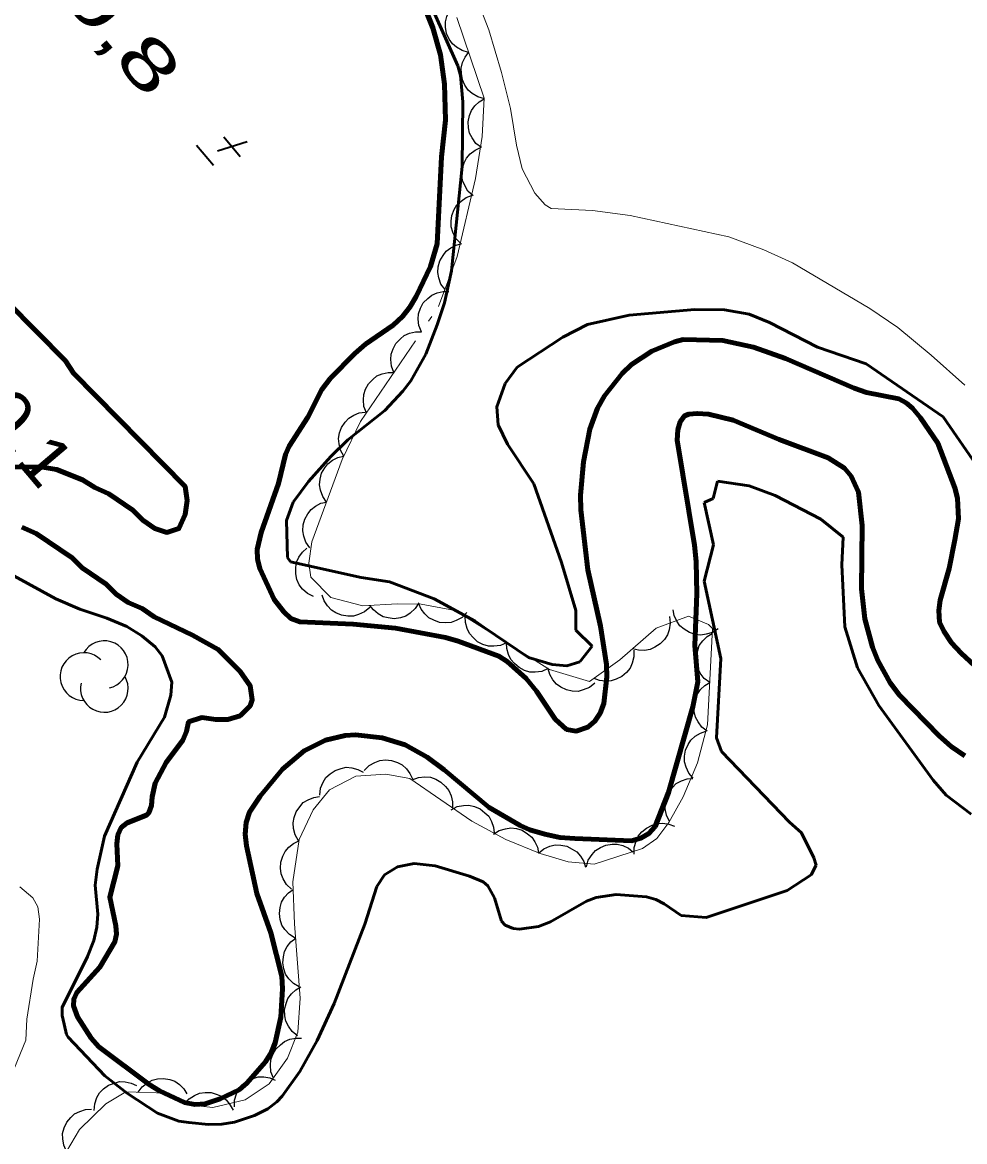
# Model space of a CAD drawing. Extents: x 386081 to 389416, y 5130568 to 5134082.
# Drawn here: x 387180.4 to 387238.2, y 5131872.3 to 5131941 of the extents above; entities that cross this region are included whole.
import ezdxf
from ezdxf.enums import TextEntityAlignment as Align

# ---------------------------------------------------------------- set-up
doc = ezdxf.new("R2010")
doc.units = 0
doc.header["$LTSCALE"] = 1.2
for name, pattern in [('DASH_DOUBLE_DOT', [9.2, 5, -1.2, 0.3, -1.2, 0.3, -1.2]), ('DOT_DASHED', [7.7, 5, -1.2, 0.3, -1.2]), ('LONG_DASHED', [7.5, 6, -1.5])]:
    doc.linetypes.add(name, pattern=pattern)
for name, color, linetype, lineweight in [('1', 7, 'Continuous', 53), ('2', 7, 'Continuous', 13), ('3', 7, 'Continuous', 140), ('4', 7, 'DASH_DOUBLE_DOT', 53), ('44', 7, 'Continuous', 25)]:
    doc.layers.add(name, color=color, linetype=linetype, lineweight=lineweight)

msp = doc.modelspace()

# ---------------------------------------------------------------- linework, layer by layer
at = {"layer": '1', "linetype": 'LONG_DASHED'}
for points in [[(387210.13, 5131915.13), (387211.73, 5131912.69), (387213.43, 5131907.87), (387214.31, 5131904.93), (387214.31, 5131903.72), (387215.31, 5131902.74), (387214.57, 5131901.78), (387213.77, 5131901.53), (387212.87, 5131901.62), (387211.41, 5131902.05), (387208.69, 5131903.88), (387208.13, 5131904.28), (387205.62, 5131905.65), (387202.88, 5131906.69), (387201.14, 5131906.95), (387196.81, 5131907.91), (387196.62, 5131908.18), (387196.56, 5131910.44), (387196.98, 5131911.58), (387197.91, 5131912.84), (387199.29, 5131914.37), (387200.32, 5131915.4), (387202.6, 5131917.2), (387203.71, 5131918.38), (387204.19, 5131919.01), (387205.11, 5131920.65), (387205.81, 5131922.45), (387206.25, 5131923.79), (387206.69, 5131925.75), (387207.34, 5131932.16), (387207.39, 5131936.13), (387207.24, 5131937.74), (387207.08, 5131938.34), (387205.57, 5131941.72)], [(387239.07, 5131913.57), (387236.84, 5131916.8), (387232.13, 5131920.05), (387229.14, 5131921.07), (387226.19, 5131922.59), (387224.94, 5131923.11), (387223.44, 5131923.37), (387221.62, 5131923.38), (387217.58, 5131923.05), (387215.03, 5131922.46), (387213.52, 5131921.7), (387210.72, 5131919.86), (387209.97, 5131918.84), (387209.46, 5131917.42), (387209.55, 5131916.32), (387210.13, 5131915.13)], [(387182.92, 5131879.54), (387183.07, 5131878.91), (387183.18, 5131878.75), (387185.43, 5131876.37), (387186.82, 5131875.29), (387188.66, 5131874.08), (387189.97, 5131873.59), (387190.57, 5131873.51), (387191.79, 5131873.4), (387192.59, 5131873.42), (387193.38, 5131873.54), (387194.6, 5131873.95), (387195.42, 5131874.36), (387195.98, 5131874.78), (387196.31, 5131875.13), (387197.39, 5131876.65), (387198.44, 5131878.55), (387199.48, 5131880.82), (387201.38, 5131885.68), (387202.11, 5131888), (387202.57, 5131888.71), (387203.38, 5131889.2), (387204.4, 5131889.41), (387205.69, 5131889.26), (387207.8, 5131888.63), (387208.63, 5131888.29), (387208.92, 5131888.03), (387209.32, 5131887.3), (387209.76, 5131885.86), (387209.99, 5131885.63), (387210.47, 5131885.42), (387210.85, 5131885.37), (387212.02, 5131885.55), (387212.77, 5131885.82), (387214.96, 5131887.09), (387215.56, 5131887.32), (387216.79, 5131887.51), (387218.66, 5131887.36), (387219.23, 5131887.19), (387219.73, 5131886.93), (387220.78, 5131886.22), (387222.32, 5131886.09), (387227.27, 5131887.74), (387228.76, 5131888.72), (387229.05, 5131889.3), (387228.92, 5131889.75), (387228.15, 5131891.29), (387227.43, 5131891.95), (387223.26, 5131896.28), (387222.95, 5131897.12), (387223.22, 5131901.98), (387222.18, 5131906.72), (387222.76, 5131908.96), (387222.19, 5131911.55), (387222.75, 5131911.8), (387223, 5131912.86), (387224.95, 5131912.58), (387226.55, 5131911.98), (387229.35, 5131910.53), (387230.72, 5131909.43), (387230.63, 5131907.72), (387230.81, 5131903.92), (387231.6, 5131901.41), (387232.9, 5131899.09), (387236.23, 5131894.51), (387237.04, 5131893.59), (387238.56, 5131892.44)]]:
    msp.add_lwpolyline(points, dxfattribs=at)
at = {"layer": '1'}
msp.add_lwpolyline([(387178.97, 5131907.52), (387182.41, 5131905.64), (387183.89, 5131905.01), (387185.55, 5131904.45), (387186.78, 5131903.94), (387187.7, 5131903.38), (387188.5, 5131902.7), (387188.93, 5131902.14), (387189.53, 5131900.53), (387189.47, 5131899.73), (387189.09, 5131898.38), (387187.4, 5131895.63), (387185.4, 5131891.09), (387184.95, 5131889.06), (387184.82, 5131888.07), (387185, 5131886.29), (387184.93, 5131885.49), (387184.74, 5131884.69), (387184.36, 5131883.71), (387182.8, 5131880.58), (387182.8, 5131880.09), (387182.92, 5131879.54)], dxfattribs=at)
at = {"layer": '2', "linetype": 'LONG_DASHED'}
msp.add_lwpolyline([(387238.17, 5131918.74), (387236.12, 5131920.58), (387234.06, 5131922.28), (387232.35, 5131923.45), (387227.6, 5131926.26), (387225.85, 5131927.04), (387223.7, 5131927.84), (387217.65, 5131929.15), (387215.33, 5131929.46), (387212.81, 5131929.59), (387212.44, 5131929.8), (387211.8, 5131930.53), (387211.03, 5131932.01), (387210.67, 5131933.47), (387210.31, 5131935.72), (387209.75, 5131937.92), (387208.98, 5131940.54), (387208.18, 5131942.59)], dxfattribs=at)
at = {"layer": '2'}
msp.add_lwpolyline([(387180.21, 5131887.98), (387181, 5131887.3), (387181.31, 5131886.74), (387181.42, 5131886), (387181.28, 5131883.42), (387181.03, 5131882.32), (387180.64, 5131879.86), (387180.57, 5131878.57), (387178.2, 5131872.82)], dxfattribs=at)
at = {"layer": '3', "lineweight": 35}
for p, q in [((387194.15, 5131933.68), (387192.33, 5131933.11)), ((387192.72, 5131933.97), (387193.73, 5131932.78)), ((387191.05, 5131933.47), (387192.09, 5131932.25))]:
    msp.add_line(p, q, dxfattribs=at)
at = {"layer": '4', "linetype": 'Continuous', "lineweight": 90}
for points in [[(387199.26, 5131919.17), (387200.76, 5131920.69), (387201.41, 5131921.26), (387203.11, 5131922.43), (387203.68, 5131922.96), (387204.14, 5131923.54), (387204.52, 5131924.19), (387205.39, 5131926.03), (387205.8, 5131927.42), (387206.07, 5131932.76), (387206.31, 5131935.01), (387206.26, 5131937.22), (387206.02, 5131939), (387205.54, 5131940.66), (387204.83, 5131942.48)], [(387179.45, 5131923.83), (387183, 5131920.23), (387183.49, 5131919.49), (387190.35, 5131912.53), (387190.47, 5131911.67), (387190.34, 5131910.81), (387189.97, 5131909.95), (387189.22, 5131909.71), (387188.49, 5131909.96), (387187.75, 5131910.46), (387187.14, 5131911.08), (387185.66, 5131912.08), (387184.8, 5131912.46), (387184.06, 5131912.95), (387182.46, 5131913.58), (387181.6, 5131913.71), (387179.63, 5131913.73)], [(387239.89, 5131900.51), (387237.95, 5131902.3), (387237.37, 5131902.95), (387236.89, 5131903.66), (387236.63, 5131904.2), (387236.58, 5131904.93), (387236.67, 5131905.55), (387237.22, 5131907.51), (387237.57, 5131909.25), (387237.78, 5131910.55), (387237.72, 5131911.82), (387237.57, 5131912.44), (387236.52, 5131915.19), (387235.46, 5131916.75), (387234.96, 5131917.34), (387234.57, 5131917.67), (387234.13, 5131917.9), (387232.15, 5131918.3), (387231.39, 5131918.57), (387227.18, 5131920.38), (387225.22, 5131921.07), (387223.34, 5131921.48), (387220.9, 5131921.54), (387220.36, 5131921.41), (387218.97, 5131920.83), (387217.73, 5131920.01), (387217.15, 5131919.46), (387216.08, 5131918.09), (387215.65, 5131917.34), (387215.18, 5131916.04), (387214.78, 5131914.05), (387214.6, 5131911.99), (387214.63, 5131911.09), (387215.05, 5131907.42), (387215.83, 5131903.96), (387216.19, 5131901.61), (387216.22, 5131900.86), (387216.03, 5131899.21), (387215.81, 5131898.63), (387215.49, 5131898.13), (387215.06, 5131897.76), (387214.33, 5131897.53), (387213.75, 5131897.63), (387213.05, 5131898.26), (387211.91, 5131899.97), (387211.27, 5131900.76), (387210.11, 5131901.8), (387209.59, 5131902.13), (387207.1, 5131903.05), (387206.33, 5131903.26), (387203.26, 5131903.84), (387200.66, 5131904.09), (387197.39, 5131904.22), (387196.83, 5131904.44), (387196.4, 5131904.84), (387195.8, 5131905.59), (387194.94, 5131907.51), (387194.79, 5131908.07), (387194.77, 5131908.66), (387195.02, 5131909.71), (387196.07, 5131912.71), (387196.51, 5131914.49), (387196.72, 5131915), (387197.87, 5131916.78), (387198.74, 5131918.49), (387199.26, 5131919.17)], [(387190.94, 5131874.62), (387191.57, 5131874.67), (387192.5, 5131874.96), (387193.66, 5131875.53), (387194.14, 5131875.93), (387195.27, 5131877.24), (387195.64, 5131877.83), (387195.88, 5131878.41), (387196.22, 5131879.97), (387196.33, 5131881.72), (387196.27, 5131882.49), (387195.6, 5131885.16), (387194.74, 5131887.57), (387194.12, 5131890.48), (387194.04, 5131891.21), (387194.1, 5131891.92), (387194.29, 5131892.55), (387194.95, 5131893.53), (387196.33, 5131895.19), (387197.64, 5131896.32), (387198.96, 5131896.97), (387200.17, 5131897.26), (387200.8, 5131897.29), (387202.43, 5131897.11), (387203.85, 5131896.69), (387205.19, 5131895.92), (387206.23, 5131895.15), (387208.99, 5131892.84), (387210.9, 5131891.74), (387211.49, 5131891.47), (387212.42, 5131891.2), (387213.33, 5131891.01), (387214.26, 5131890.94), (387217.74, 5131890.8), (387218.3, 5131890.95), (387218.8, 5131891.25), (387219.18, 5131891.68), (387219.99, 5131893.76), (387221.49, 5131899.01), (387221.79, 5131900.55), (387221.61, 5131902.8), (387221.74, 5131905.95), (387221.69, 5131907.92), (387221.6, 5131908.93), (387220.53, 5131915.37), (387220.58, 5131916), (387220.72, 5131916.5), (387220.98, 5131916.86), (387221.25, 5131916.97), (387221.76, 5131917.01), (387222.45, 5131916.97), (387223.96, 5131916.61), (387226.78, 5131915.42), (387229.8, 5131914.29), (387230.8, 5131913.65), (387231.2, 5131913.16), (387231.65, 5131912.19), (387231.89, 5131910.13), (387231.83, 5131906.26), (387232.05, 5131904.42), (387232.52, 5131902.67), (387232.84, 5131901.86), (387233.59, 5131900.49), (387234.17, 5131899.73), (387236.61, 5131897.23), (387237.34, 5131896.59), (387238.17, 5131896.01)], [(387180.34, 5131910.03), (387181.2, 5131909.65), (387183.41, 5131908.16), (387184.03, 5131907.54), (387185.5, 5131906.54), (387186.11, 5131905.92), (387186.85, 5131905.42), (387187.71, 5131905.04), (387188.45, 5131904.54), (387190.79, 5131903.42), (387192.38, 5131902.54), (387193.73, 5131901.18), (387194.34, 5131900.31), (387194.46, 5131899.45), (387194.34, 5131899.08), (387193.72, 5131898.47), (387192.97, 5131898.23), (387192.23, 5131898.23), (387191.37, 5131898.36), (387190.56, 5131898.09), (387190.44, 5131897.51), (387190.2, 5131896.97), (387189.18, 5131895.61), (387188.51, 5131894.33), (387188.32, 5131893.5), (387188.29, 5131892.96), (387188.12, 5131892.51), (387187.97, 5131892.36), (387186.8, 5131891.9), (387186.42, 5131891.61), (387186.22, 5131891.16), (387186.15, 5131890.62), (387186.21, 5131889.26), (387185.72, 5131887.34), (387186.1, 5131885.59), (387186.14, 5131885.07), (387186.04, 5131884.59), (387185.11, 5131883.04), (387183.7, 5131881.5), (387183.52, 5131881.09), (387183.5, 5131880.68), (387183.75, 5131879.99), (387184.58, 5131878.7), (387185.05, 5131878.16), (387188.14, 5131875.84), (387188.78, 5131875.45), (387190.31, 5131874.75), (387190.94, 5131874.62)]]:
    msp.add_lwpolyline(points, dxfattribs=at)
at = {"layer": '44'}
for points in [[(387207.74, 5131939.16), (387207.34, 5131939.27), (387206.99, 5131939.48), (387206.74, 5131939.69), (387206.54, 5131939.98), (387206.39, 5131940.32), (387206.33, 5131940.7), (387206.31, 5131941.03), (387206.4, 5131941.37), (387206.55, 5131941.71), (387206.77, 5131941.99)], [(387208.71, 5131936.32), (387208.31, 5131936.43), (387207.96, 5131936.64), (387207.71, 5131936.85), (387207.51, 5131937.15), (387207.36, 5131937.48), (387207.3, 5131937.86), (387207.28, 5131938.19), (387207.37, 5131938.53), (387207.52, 5131938.87), (387207.74, 5131939.16)], [(387208.52, 5131933.32), (387208.19, 5131933.58), (387207.95, 5131933.91), (387207.8, 5131934.2), (387207.73, 5131934.54), (387207.72, 5131934.91), (387207.8, 5131935.29), (387207.91, 5131935.59), (387208.12, 5131935.88), (387208.39, 5131936.13), (387208.7, 5131936.32)], [(387208.01, 5131930.36), (387207.7, 5131930.64), (387207.5, 5131930.99), (387207.37, 5131931.3), (387207.33, 5131931.65), (387207.35, 5131932.02), (387207.47, 5131932.38), (387207.61, 5131932.68), (387207.84, 5131932.94), (387208.13, 5131933.17), (387208.46, 5131933.33)], [(387207.23, 5131927.46), (387206.94, 5131927.77), (387206.77, 5131928.13), (387206.67, 5131928.45), (387206.66, 5131928.8), (387206.71, 5131929.16), (387206.86, 5131929.52), (387207.02, 5131929.8), (387207.28, 5131930.04), (387207.58, 5131930.25), (387207.92, 5131930.38)], [(387206.29, 5131924.62), (387206.04, 5131924.95), (387205.91, 5131925.34), (387205.85, 5131925.66), (387205.88, 5131926.01), (387205.98, 5131926.37), (387206.17, 5131926.7), (387206.36, 5131926.97), (387206.65, 5131927.18), (387206.98, 5131927.34), (387207.33, 5131927.43)], [(387204.84, 5131922.01), (387204.69, 5131922.4), (387204.65, 5131922.8), (387204.67, 5131923.13), (387204.78, 5131923.46), (387204.96, 5131923.79), (387205.23, 5131924.06), (387205.48, 5131924.27), (387205.8, 5131924.41), (387206.17, 5131924.49), (387206.53, 5131924.49)], [(387203.16, 5131919.53), (387203, 5131919.91), (387202.97, 5131920.32), (387202.98, 5131920.65), (387203.1, 5131920.98), (387203.28, 5131921.3), (387203.55, 5131921.58), (387203.79, 5131921.79), (387204.12, 5131921.93), (387204.48, 5131922.01), (387204.84, 5131922.01)], [(387201.47, 5131917.04), (387201.32, 5131917.43), (387201.28, 5131917.84), (387201.3, 5131918.17), (387201.42, 5131918.5), (387201.6, 5131918.82), (387201.86, 5131919.1), (387202.11, 5131919.31), (387202.44, 5131919.44), (387202.8, 5131919.53), (387203.16, 5131919.53)], [(387200.09, 5131914.39), (387199.88, 5131914.75), (387199.79, 5131915.14), (387199.75, 5131915.47), (387199.82, 5131915.82), (387199.95, 5131916.16), (387200.17, 5131916.48), (387200.39, 5131916.72), (387200.69, 5131916.9), (387201.03, 5131917.04), (387201.39, 5131917.09)], [(387199.03, 5131911.58), (387198.79, 5131911.92), (387198.66, 5131912.31), (387198.59, 5131912.63), (387198.63, 5131912.98), (387198.72, 5131913.34), (387198.92, 5131913.67), (387199.11, 5131913.93), (387199.39, 5131914.14), (387199.72, 5131914.31), (387200.07, 5131914.4)], [(387198, 5131908.77), (387197.75, 5131909.11), (387197.62, 5131909.49), (387197.56, 5131909.81), (387197.59, 5131910.17), (387197.69, 5131910.52), (387197.88, 5131910.85), (387198.07, 5131911.12), (387198.35, 5131911.33), (387198.68, 5131911.5), (387199.03, 5131911.58)], [(387198.23, 5131905.78), (387197.85, 5131905.96), (387197.55, 5131906.24), (387197.34, 5131906.49), (387197.21, 5131906.82), (387197.13, 5131907.18), (387197.14, 5131907.56), (387197.18, 5131907.88), (387197.33, 5131908.2), (387197.54, 5131908.51), (387197.81, 5131908.75)], [(387201.67, 5131905.11), (387201.35, 5131904.84), (387200.98, 5131904.67), (387200.67, 5131904.57), (387200.32, 5131904.57), (387199.95, 5131904.63), (387199.6, 5131904.79), (387199.32, 5131904.95), (387199.08, 5131905.21), (387198.88, 5131905.52), (387198.76, 5131905.86)], [(387204.68, 5131905.4), (387204.46, 5131905.04), (387204.16, 5131904.77), (387203.89, 5131904.58), (387203.55, 5131904.48), (387203.18, 5131904.42), (387202.8, 5131904.47), (387202.49, 5131904.54), (387202.18, 5131904.72), (387201.9, 5131904.96), (387201.68, 5131905.24)], [(387207.63, 5131904.8), (387207.34, 5131904.5), (387206.98, 5131904.31), (387206.67, 5131904.19), (387206.32, 5131904.16), (387205.96, 5131904.19), (387205.6, 5131904.33), (387205.3, 5131904.47), (387205.05, 5131904.71), (387204.83, 5131905.01), (387204.68, 5131905.34)], [(387223.05, 5131903.81), (387222.7, 5131903.58), (387222.31, 5131903.47), (387221.98, 5131903.42), (387221.64, 5131903.46), (387221.28, 5131903.57), (387220.96, 5131903.78), (387220.7, 5131903.98), (387220.51, 5131904.27), (387220.35, 5131904.61), (387220.28, 5131904.96)], [(387210.07, 5131902.95), (387209.69, 5131902.78), (387209.29, 5131902.73), (387208.96, 5131902.74), (387208.62, 5131902.84), (387208.29, 5131903.01), (387208.01, 5131903.27), (387207.79, 5131903.51), (387207.64, 5131903.83), (387207.55, 5131904.19), (387207.53, 5131904.55)], [(387220.06, 5131904.56), (387220.11, 5131904.14), (387220.04, 5131903.74), (387219.94, 5131903.43), (387219.75, 5131903.14), (387219.49, 5131902.87), (387219.17, 5131902.67), (387218.87, 5131902.53), (387218.52, 5131902.48), (387218.15, 5131902.49), (387217.8, 5131902.58)], [(387222.53, 5131900.51), (387222.19, 5131900.76), (387221.95, 5131901.09), (387221.8, 5131901.38), (387221.72, 5131901.73), (387221.71, 5131902.1), (387221.79, 5131902.47), (387221.89, 5131902.78), (387222.1, 5131903.06), (387222.37, 5131903.32), (387222.67, 5131903.51)], [(387212.62, 5131901.36), (387212.23, 5131901.19), (387211.83, 5131901.14), (387211.5, 5131901.14), (387211.16, 5131901.25), (387210.83, 5131901.42), (387210.55, 5131901.67), (387210.33, 5131901.91), (387210.18, 5131902.23), (387210.09, 5131902.59), (387210.07, 5131902.95)], [(387217.87, 5131902.5), (387217.88, 5131902.09), (387217.77, 5131901.69), (387217.64, 5131901.39), (387217.42, 5131901.12), (387217.14, 5131900.88), (387216.79, 5131900.71), (387216.48, 5131900.6), (387216.13, 5131900.59), (387215.76, 5131900.63), (387215.43, 5131900.76)], [(387215.48, 5131900.46), (387215.15, 5131900.2), (387214.77, 5131900.05), (387214.45, 5131899.96), (387214.1, 5131899.98), (387213.74, 5131900.05), (387213.4, 5131900.22), (387213.12, 5131900.4), (387212.9, 5131900.67), (387212.71, 5131900.99), (387212.61, 5131901.34)], [(387222.38, 5131897.52), (387222.05, 5131897.77), (387221.81, 5131898.1), (387221.65, 5131898.39), (387221.58, 5131898.73), (387221.56, 5131899.1), (387221.64, 5131899.47), (387221.75, 5131899.78), (387221.96, 5131900.07), (387222.22, 5131900.33), (387222.53, 5131900.51)], [(387221.51, 5131894.63), (387221.24, 5131894.95), (387221.08, 5131895.32), (387220.98, 5131895.64), (387220.99, 5131895.99), (387221.05, 5131896.36), (387221.21, 5131896.7), (387221.38, 5131896.98), (387221.64, 5131897.22), (387221.96, 5131897.41), (387222.3, 5131897.53)], [(387198.61, 5131893.6), (387198.66, 5131894.02), (387198.81, 5131894.39), (387198.98, 5131894.68), (387199.24, 5131894.91), (387199.55, 5131895.12), (387199.91, 5131895.24), (387200.23, 5131895.31), (387200.58, 5131895.27), (387200.94, 5131895.18), (387201.26, 5131895.01)], [(387201.34, 5131895.11), (387201.63, 5131895.41), (387201.98, 5131895.61), (387202.29, 5131895.73), (387202.64, 5131895.76), (387203.01, 5131895.73), (387203.37, 5131895.6), (387203.66, 5131895.46), (387203.92, 5131895.22), (387204.14, 5131894.92), (387204.29, 5131894.59)], [(387204.27, 5131894.53), (387204.66, 5131894.69), (387205.06, 5131894.72), (387205.39, 5131894.7), (387205.72, 5131894.58), (387206.04, 5131894.4), (387206.32, 5131894.13), (387206.53, 5131893.88), (387206.66, 5131893.56), (387206.74, 5131893.19), (387206.74, 5131892.83)], [(387220.06, 5131891.99), (387219.87, 5131892.36), (387219.8, 5131892.76), (387219.78, 5131893.09), (387219.87, 5131893.43), (387220.02, 5131893.77), (387220.25, 5131894.07), (387220.48, 5131894.31), (387220.79, 5131894.47), (387221.15, 5131894.59), (387221.5, 5131894.62)], [(387197.31, 5131890.8), (387197.1, 5131891.16), (387197, 5131891.56), (387196.97, 5131891.89), (387197.03, 5131892.23), (387197.16, 5131892.58), (387197.38, 5131892.89), (387197.59, 5131893.14), (387197.9, 5131893.32), (387198.24, 5131893.46), (387198.6, 5131893.51)], [(387206.66, 5131892.7), (387207.03, 5131892.9), (387207.43, 5131892.97), (387207.76, 5131892.99), (387208.1, 5131892.91), (387208.44, 5131892.76), (387208.74, 5131892.52), (387208.98, 5131892.3), (387209.14, 5131891.99), (387209.26, 5131891.63), (387209.3, 5131891.28)], [(387217.9, 5131889.97), (387217.9, 5131890.38), (387218.01, 5131890.77), (387218.14, 5131891.08), (387218.37, 5131891.35), (387218.65, 5131891.58), (387219, 5131891.75), (387219.3, 5131891.86), (387219.66, 5131891.87), (387220.02, 5131891.82), (387220.36, 5131891.69)], [(387209.26, 5131891.2), (387209.61, 5131891.43), (387210, 5131891.54), (387210.33, 5131891.59), (387210.68, 5131891.55), (387211.03, 5131891.44), (387211.35, 5131891.23), (387211.61, 5131891.03), (387211.81, 5131890.74), (387211.96, 5131890.4), (387212.03, 5131890.05)], [(387196.88, 5131887.83), (387196.57, 5131888.11), (387196.37, 5131888.46), (387196.24, 5131888.77), (387196.2, 5131889.12), (387196.22, 5131889.49), (387196.34, 5131889.85), (387196.48, 5131890.15), (387196.71, 5131890.41), (387197, 5131890.64), (387197.33, 5131890.8)], [(387212.03, 5131890.04), (387212.35, 5131890.3), (387212.73, 5131890.46), (387213.05, 5131890.54), (387213.4, 5131890.53), (387213.76, 5131890.46), (387214.1, 5131890.29), (387214.38, 5131890.12), (387214.61, 5131889.85), (387214.8, 5131889.53), (387214.9, 5131889.18)], [(387214.97, 5131889.21), (387215.08, 5131889.61), (387215.31, 5131889.95), (387215.52, 5131890.2), (387215.82, 5131890.39), (387216.16, 5131890.53), (387216.54, 5131890.59), (387216.86, 5131890.6), (387217.2, 5131890.51), (387217.54, 5131890.35), (387217.82, 5131890.13)], [(387197.1, 5131884.83), (387196.74, 5131885.05), (387196.47, 5131885.35), (387196.29, 5131885.63), (387196.18, 5131885.96), (387196.14, 5131886.33), (387196.18, 5131886.71), (387196.26, 5131887.03), (387196.44, 5131887.33), (387196.68, 5131887.61), (387196.97, 5131887.82)], [(387197.35, 5131881.84), (387196.99, 5131882.05), (387196.71, 5131882.34), (387196.51, 5131882.61), (387196.4, 5131882.94), (387196.34, 5131883.31), (387196.38, 5131883.69), (387196.44, 5131884.01), (387196.61, 5131884.32), (387196.84, 5131884.61), (387197.13, 5131884.83)], [(387197.25, 5131878.84), (387196.92, 5131879.1), (387196.68, 5131879.43), (387196.53, 5131879.73), (387196.46, 5131880.07), (387196.45, 5131880.44), (387196.54, 5131880.81), (387196.65, 5131881.12), (387196.87, 5131881.4), (387197.14, 5131881.66), (387197.45, 5131881.84)], [(387195.76, 5131876.24), (387195.61, 5131876.63), (387195.59, 5131877.04), (387195.61, 5131877.37), (387195.73, 5131877.69), (387195.92, 5131878.01), (387196.19, 5131878.29), (387196.44, 5131878.49), (387196.77, 5131878.62), (387197.13, 5131878.7), (387197.49, 5131878.69)], [(387184.77, 5131874.25), (387184.8, 5131874.67), (387184.94, 5131875.05), (387185.1, 5131875.34), (387185.35, 5131875.59), (387185.65, 5131875.81), (387186.01, 5131875.94), (387186.32, 5131876.03), (387186.67, 5131876.01), (387187.03, 5131875.93), (387187.36, 5131875.78)], [(387187.46, 5131875.38), (387187.71, 5131875.71), (387188.03, 5131875.96), (387188.32, 5131876.12), (387188.66, 5131876.2), (387189.03, 5131876.22), (387189.41, 5131876.15), (387189.72, 5131876.05), (387190, 5131875.85), (387190.27, 5131875.59), (387190.46, 5131875.28)], [(387193.37, 5131874.48), (387193.37, 5131874.89), (387193.5, 5131875.28), (387193.64, 5131875.58), (387193.87, 5131875.84), (387194.17, 5131876.07), (387194.52, 5131876.22), (387194.83, 5131876.32), (387195.18, 5131876.32), (387195.55, 5131876.26), (387195.88, 5131876.12)], [(387190.31, 5131874.65), (387190.59, 5131874.97), (387190.93, 5131875.18), (387191.23, 5131875.31), (387191.58, 5131875.36), (387191.95, 5131875.35), (387192.32, 5131875.23), (387192.62, 5131875.11), (387192.89, 5131874.88), (387193.12, 5131874.59), (387193.29, 5131874.27)], [(387183.08, 5131871.74), (387182.9, 5131872.12), (387182.84, 5131872.52), (387182.83, 5131872.85), (387182.93, 5131873.19), (387183.09, 5131873.53), (387183.33, 5131873.82), (387183.57, 5131874.04), (387183.89, 5131874.2), (387184.24, 5131874.31), (387184.6, 5131874.33)]]:
    msp.add_lwpolyline(points, dxfattribs=at)
at = {"layer": '44', "linetype": 'DOT_DASHED', "lineweight": 13}
msp.add_lwpolyline([(387182.5, 5131870.77), (387183.87, 5131873.09), (387185.48, 5131874.67), (387186.72, 5131875.4), (387189.23, 5131875.32), (387190.95, 5131874.57), (387192.05, 5131874.43), (387194.03, 5131874.91), (387195.51, 5131875.88), (387196.63, 5131877.47), (387197.26, 5131879.06), (387197.4, 5131881.15), (387197.06, 5131885.7), (387196.95, 5131888.29), (387197.34, 5131890.87), (387198.21, 5131892.7), (387199.21, 5131893.92), (387200.81, 5131894.77), (387202.66, 5131894.88), (387204.14, 5131894.62), (387207.94, 5131892.01), (387210.03, 5131890.88), (387212.12, 5131890.01), (387213.84, 5131889.5), (387215.44, 5131889.36), (387218.41, 5131890.32), (387219.28, 5131890.93), (387220.02, 5131891.91), (387220.89, 5131893.5), (387221.77, 5131895.58), (387222.4, 5131897.91), (387222.69, 5131903.82), (387222.45, 5131904.06), (387221.22, 5131904.57), (387219.24, 5131903.84), (387217.01, 5131901.89), (387215.15, 5131900.56), (387212.69, 5131901.31), (387206.92, 5131904.93), (387204.83, 5131905.31), (387203.35, 5131905.33), (387201.25, 5131905.22), (387199.28, 5131905.73), (387198.06, 5131906.97), (387197.94, 5131907.83), (387198.13, 5131909.13), (387199.99, 5131914.18), (387201.11, 5131916.51), (387205.9, 5131923.57), (387207.03, 5131926.63), (387208.17, 5131931.43), (387208.56, 5131934.01), (387208.7, 5131936.35), (387207.01, 5131941.29)], dxfattribs=at)
at = {"layer": '44'}
for centre, start, end in [((387185.39, 5131901.603), 282.26917, 149.72626), ((387184.134, 5131900.873), 44.11537, 269.80396), ((387185.39, 5131900.143), 166.93686, 29.62122)]:
    msp.add_arc(centre, 1.46, start, end, dxfattribs=at)

# ---------------------------------------------------------------- texts
at = {"layer": '3', "width": 1.5}
msp.add_text('    9,8', height=3, rotation=310.294, dxfattribs=at).set_placement((387183.188, 5131941.935), align=Align.CENTER)
at = {"layer": '3', "width": 1.1}
msp.add_text('10,1   ', height=3, rotation=310.294, dxfattribs=at).set_placement((387175.92, 5131918.78))

doc.saveas('drawing.dxf')
